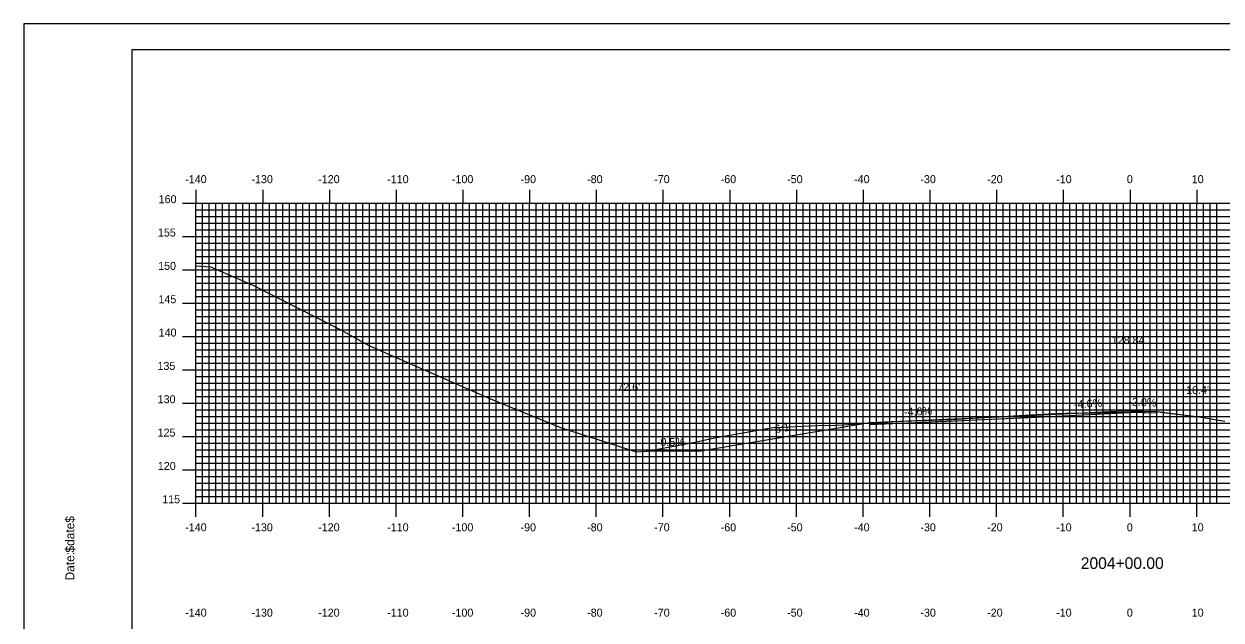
# Model space of a CAD drawing. Extents: x 851533 to 851876, y 366605 to 366825.
# Drawn here: x 851532.7 to 851712.1, y 366735.5 to 366824.9 of the extents above; entities that cross this region are included whole.
import ezdxf

# ---------------------------------------------------------------- set-up
doc = ezdxf.new("R2010")
doc.units = 0
for name, color, linetype in [('ANNOTATION', 7, 'Continuous'), ('BORDER', 7, 'Continuous'), ('D_Roadway_Centerline_Text', 7, 'Continuous'), ('D_Roadway_Edge_Shoulder', 7, 'Continuous'), ('D_Roadway_Edge_TW', 7, 'Continuous'), ('D_Roadway_SlopeLines', 7, 'Continuous'), ('D_Text_Standard', 7, 'Continuous'), ('H_V ANNOTATION', 7, 'Continuous'), ('M_Roadway_Centerline', 7, 'Continuous'), ('MAJOR', 7, 'Continuous'), ('MINOR', 7, 'Continuous'), ('PLOT BOUNDARY', 7, 'Continuous'), ('S_Roadway_Centerline', 7, 'Continuous')]:
    doc.layers.add(name, color=color, linetype=linetype)

msp = doc.modelspace()

# ---------------------------------------------------------------- linework, layer by layer
at = {"layer": 'BORDER'}
msp.add_lwpolyline([(851548.85, 366611.06), (851868.85, 366611.06), (851868.85, 366821.06), (851548.85, 366821.06)], close=True, dxfattribs=at)
at = {"layer": 'D_Roadway_Edge_Shoulder'}
for points in [[(851698.45, 366766.9), (851702.45, 366766.82), (851702.45, 366766.57), (851698.45, 366766.65)], [(851667.46, 366765.47), (851659.46, 366765.1), (851659.46, 366764.85), (851667.46, 366765.22)]]:
    msp.add_lwpolyline(points, close=True, dxfattribs=at)
at = {"layer": 'D_Roadway_Edge_TW'}
for points in [[(851698.45, 366766.9), (851686.45, 366766.34), (851686.45, 366766.09), (851698.45, 366766.65)], [(851674.45, 366765.79), (851667.46, 366765.47), (851667.46, 366765.22), (851674.45, 366765.54)], [(851686.45, 366766.34), (851674.45, 366765.79), (851674.45, 366765.54), (851686.45, 366766.09)]]:
    msp.add_lwpolyline(points, close=True, dxfattribs=at)
msp.add_lwpolyline([(851674.45, 366765.54), (851674.45, 366765.79)], dxfattribs=at)
at = {"layer": 'D_Roadway_SlopeLines'}
msp.add_line((851702.45, 366766.82), (851708.81, 366766), dxfattribs=at)
for points in [[(851659.46, 366765.1), (851633.83, 366760.83)], [(851633.83, 366760.83), (851625.88, 366760.87)]]:
    msp.add_lwpolyline(points, dxfattribs=at)
at = {"layer": 'MAJOR'}
for p, q in [((851558.45, 366800.06), (851558.45, 366798.06)), ((851568.45, 366800.06), (851568.45, 366798.06)), ((851578.45, 366800.06), (851578.45, 366798.06)), ((851588.45, 366800.06), (851588.45, 366798.06)), ((851598.45, 366800.06), (851598.45, 366798.06)), ((851608.45, 366800.06), (851608.45, 366798.06)), ((851618.45, 366800.06), (851618.45, 366798.06)), ((851628.45, 366800.06), (851628.45, 366798.06)), ((851638.45, 366800.06), (851638.45, 366798.06)), ((851648.45, 366800.06), (851648.45, 366798.06)), ((851658.45, 366800.06), (851658.45, 366798.06)), ((851668.45, 366800.06), (851668.45, 366798.06)), ((851678.45, 366800.06), (851678.45, 366798.06)), ((851688.45, 366800.06), (851688.45, 366798.06)), ((851698.45, 366800.06), (851698.45, 366798.06)), ((851708.45, 366800.06), (851708.45, 366798.06)), ((851556.45, 366798.06), (851558.45, 366798.06)), ((851558.45, 366798.06), (851838.45, 366798.06)), ((851558.45, 366753.06), (851558.45, 366798.06)), ((851558.45, 366753.06), (851558.45, 366798.06)), ((851558.45, 366798.06), (851838.45, 366798.06)), ((851568.45, 366753.06), (851568.45, 366798.06)), ((851578.45, 366753.06), (851578.45, 366798.06)), ((851588.45, 366753.06), (851588.45, 366798.06)), ((851598.45, 366753.06), (851598.45, 366798.06)), ((851608.45, 366753.06), (851608.45, 366798.06)), ((851618.45, 366753.06), (851618.45, 366798.06)), ((851628.45, 366753.06), (851628.45, 366798.06)), ((851638.45, 366753.06), (851638.45, 366798.06)), ((851648.45, 366753.06), (851648.45, 366798.06)), ((851658.45, 366753.06), (851658.45, 366798.06)), ((851668.45, 366753.06), (851668.45, 366798.06)), ((851678.45, 366753.06), (851678.45, 366798.06)), ((851688.45, 366753.06), (851688.45, 366798.06)), ((851698.45, 366753.06), (851698.45, 366798.06)), ((851708.45, 366753.06), (851708.45, 366798.06)), ((851556.45, 366793.06), (851558.45, 366793.06)), ((851558.45, 366793.06), (851838.45, 366793.06)), ((851556.45, 366788.06), (851558.45, 366788.06)), ((851558.45, 366788.06), (851838.45, 366788.06)), ((851556.45, 366783.06), (851558.45, 366783.06)), ((851558.45, 366783.06), (851838.45, 366783.06)), ((851556.45, 366778.06), (851558.45, 366778.06)), ((851558.45, 366778.06), (851838.45, 366778.06)), ((851556.45, 366773.06), (851558.45, 366773.06)), ((851558.45, 366773.06), (851838.45, 366773.06)), ((851556.45, 366768.06), (851558.45, 366768.06)), ((851558.45, 366768.06), (851838.45, 366768.06)), ((851556.45, 366763.06), (851558.45, 366763.06)), ((851558.45, 366763.06), (851838.45, 366763.06)), ((851556.45, 366758.06), (851558.45, 366758.06)), ((851558.45, 366758.06), (851838.45, 366758.06)), ((851556.45, 366753.06), (851558.45, 366753.06)), ((851558.45, 366753.06), (851838.45, 366753.06)), ((851558.45, 366753.06), (851838.45, 366753.06)), ((851558.45, 366751.05), (851558.45, 366753.06)), ((851568.45, 366751.05), (851568.45, 366753.06)), ((851578.45, 366751.05), (851578.45, 366753.06)), ((851588.45, 366751.05), (851588.45, 366753.06)), ((851598.45, 366751.05), (851598.45, 366753.06)), ((851608.45, 366751.05), (851608.45, 366753.06)), ((851618.45, 366751.05), (851618.45, 366753.06)), ((851628.45, 366751.05), (851628.45, 366753.06)), ((851638.45, 366751.05), (851638.45, 366753.06)), ((851648.45, 366751.05), (851648.45, 366753.06)), ((851658.45, 366751.05), (851658.45, 366753.06)), ((851668.45, 366751.05), (851668.45, 366753.06)), ((851678.45, 366751.05), (851678.45, 366753.06)), ((851688.45, 366751.05), (851688.45, 366753.06)), ((851698.45, 366751.05), (851698.45, 366753.06)), ((851708.45, 366751.05), (851708.45, 366753.06))]:
    msp.add_line(p, q, dxfattribs=at)
at = {"layer": 'MINOR'}
for p, q in [((851559.45, 366753.06), (851559.45, 366798.06)), ((851560.45, 366753.06), (851560.45, 366798.06)), ((851561.45, 366753.06), (851561.45, 366798.06)), ((851562.45, 366753.06), (851562.45, 366798.06)), ((851563.45, 366753.06), (851563.45, 366798.06)), ((851564.45, 366753.06), (851564.45, 366798.06)), ((851565.45, 366753.06), (851565.45, 366798.06)), ((851566.45, 366753.06), (851566.45, 366798.06)), ((851567.45, 366753.06), (851567.45, 366798.06)), ((851569.45, 366753.06), (851569.45, 366798.06)), ((851570.45, 366753.06), (851570.45, 366798.06)), ((851571.45, 366753.06), (851571.45, 366798.06)), ((851572.45, 366753.06), (851572.45, 366798.06)), ((851573.45, 366753.06), (851573.45, 366798.06)), ((851574.45, 366753.06), (851574.45, 366798.06)), ((851575.45, 366753.06), (851575.45, 366798.06)), ((851576.45, 366753.06), (851576.45, 366798.06)), ((851577.45, 366753.06), (851577.45, 366798.06)), ((851579.45, 366753.06), (851579.45, 366798.06)), ((851580.45, 366753.06), (851580.45, 366798.06)), ((851581.45, 366753.06), (851581.45, 366798.06)), ((851582.45, 366753.06), (851582.45, 366798.06)), ((851583.45, 366753.06), (851583.45, 366798.06)), ((851584.45, 366753.06), (851584.45, 366798.06)), ((851585.45, 366753.06), (851585.45, 366798.06)), ((851586.45, 366753.06), (851586.45, 366798.06)), ((851587.45, 366753.06), (851587.45, 366798.06)), ((851589.45, 366753.06), (851589.45, 366798.06)), ((851590.45, 366753.06), (851590.45, 366798.06)), ((851591.45, 366753.06), (851591.45, 366798.06)), ((851592.45, 366753.06), (851592.45, 366798.06)), ((851593.45, 366753.06), (851593.45, 366798.06)), ((851594.45, 366753.06), (851594.45, 366798.06)), ((851595.45, 366753.06), (851595.45, 366798.06)), ((851596.45, 366753.06), (851596.45, 366798.06)), ((851597.45, 366753.06), (851597.45, 366798.06)), ((851599.45, 366753.06), (851599.45, 366798.06)), ((851600.45, 366753.06), (851600.45, 366798.06)), ((851601.45, 366753.06), (851601.45, 366798.06)), ((851602.45, 366753.06), (851602.45, 366798.06)), ((851603.45, 366753.06), (851603.45, 366798.06)), ((851604.45, 366753.06), (851604.45, 366798.06)), ((851605.45, 366753.06), (851605.45, 366798.06)), ((851606.45, 366753.06), (851606.45, 366798.06)), ((851607.45, 366753.06), (851607.45, 366798.06)), ((851609.45, 366753.06), (851609.45, 366798.06)), ((851610.45, 366753.06), (851610.45, 366798.06)), ((851611.45, 366753.06), (851611.45, 366798.06)), ((851612.45, 366753.06), (851612.45, 366798.06)), ((851613.45, 366753.06), (851613.45, 366798.06)), ((851614.45, 366753.06), (851614.45, 366798.06)), ((851615.45, 366753.06), (851615.45, 366798.06)), ((851616.45, 366753.06), (851616.45, 366798.06)), ((851617.45, 366753.06), (851617.45, 366798.06)), ((851619.45, 366753.06), (851619.45, 366798.06)), ((851620.45, 366753.06), (851620.45, 366798.06)), ((851621.45, 366753.06), (851621.45, 366798.06)), ((851622.45, 366753.06), (851622.45, 366798.06)), ((851623.45, 366753.06), (851623.45, 366798.06)), ((851624.45, 366753.06), (851624.45, 366798.06)), ((851625.45, 366753.06), (851625.45, 366798.06)), ((851626.45, 366753.06), (851626.45, 366798.06)), ((851627.45, 366753.06), (851627.45, 366798.06)), ((851629.45, 366753.06), (851629.45, 366798.06)), ((851630.45, 366753.06), (851630.45, 366798.06)), ((851631.45, 366753.06), (851631.45, 366798.06)), ((851632.45, 366753.06), (851632.45, 366798.06)), ((851633.45, 366753.06), (851633.45, 366798.06)), ((851634.45, 366753.06), (851634.45, 366798.06)), ((851635.45, 366753.06), (851635.45, 366798.06)), ((851636.45, 366753.06), (851636.45, 366798.06)), ((851637.45, 366753.06), (851637.45, 366798.06)), ((851639.45, 366753.06), (851639.45, 366798.06)), ((851640.45, 366753.06), (851640.45, 366798.06)), ((851641.45, 366753.06), (851641.45, 366798.06)), ((851642.45, 366753.06), (851642.45, 366798.06)), ((851643.45, 366753.06), (851643.45, 366798.06)), ((851644.45, 366753.06), (851644.45, 366798.06)), ((851645.45, 366753.06), (851645.45, 366798.06)), ((851646.45, 366753.06), (851646.45, 366798.06)), ((851647.45, 366753.06), (851647.45, 366798.06)), ((851649.45, 366753.06), (851649.45, 366798.06)), ((851650.45, 366753.06), (851650.45, 366798.06)), ((851651.45, 366753.06), (851651.45, 366798.06)), ((851652.45, 366753.06), (851652.45, 366798.06)), ((851653.45, 366753.06), (851653.45, 366798.06)), ((851654.45, 366753.06), (851654.45, 366798.06)), ((851655.45, 366753.06), (851655.45, 366798.06)), ((851656.45, 366753.06), (851656.45, 366798.06)), ((851657.45, 366753.06), (851657.45, 366798.06)), ((851659.45, 366753.06), (851659.45, 366798.06)), ((851660.45, 366753.06), (851660.45, 366798.06)), ((851661.45, 366753.06), (851661.45, 366798.06)), ((851662.45, 366753.06), (851662.45, 366798.06)), ((851663.45, 366753.06), (851663.45, 366798.06)), ((851664.45, 366753.06), (851664.45, 366798.06)), ((851665.45, 366753.06), (851665.45, 366798.06)), ((851666.45, 366753.06), (851666.45, 366798.06)), ((851667.45, 366753.06), (851667.45, 366798.06)), ((851669.45, 366753.06), (851669.45, 366798.06)), ((851670.45, 366753.06), (851670.45, 366798.06)), ((851671.45, 366753.06), (851671.45, 366798.06)), ((851672.45, 366753.06), (851672.45, 366798.06)), ((851673.45, 366753.06), (851673.45, 366798.06)), ((851674.45, 366753.06), (851674.45, 366798.06)), ((851675.45, 366753.06), (851675.45, 366798.06)), ((851676.45, 366753.06), (851676.45, 366798.06)), ((851677.45, 366753.06), (851677.45, 366798.06)), ((851679.45, 366753.06), (851679.45, 366798.06)), ((851680.45, 366753.06), (851680.45, 366798.06)), ((851681.45, 366753.06), (851681.45, 366798.06)), ((851682.45, 366753.06), (851682.45, 366798.06)), ((851683.45, 366753.06), (851683.45, 366798.06)), ((851684.45, 366753.06), (851684.45, 366798.06)), ((851685.45, 366753.06), (851685.45, 366798.06)), ((851686.45, 366753.06), (851686.45, 366798.06)), ((851687.45, 366753.06), (851687.45, 366798.06)), ((851689.45, 366753.06), (851689.45, 366798.06)), ((851690.45, 366753.06), (851690.45, 366798.06)), ((851691.45, 366753.06), (851691.45, 366798.06)), ((851692.45, 366753.06), (851692.45, 366798.06)), ((851693.45, 366753.06), (851693.45, 366798.06)), ((851694.45, 366753.06), (851694.45, 366798.06)), ((851695.45, 366753.06), (851695.45, 366798.06)), ((851696.45, 366753.06), (851696.45, 366798.06)), ((851697.45, 366753.06), (851697.45, 366798.06)), ((851699.45, 366753.06), (851699.45, 366798.06)), ((851700.45, 366753.06), (851700.45, 366798.06)), ((851701.45, 366753.06), (851701.45, 366798.06)), ((851702.45, 366753.06), (851702.45, 366798.06)), ((851703.45, 366753.06), (851703.45, 366798.06)), ((851704.45, 366753.06), (851704.45, 366798.06)), ((851705.45, 366753.06), (851705.45, 366798.06)), ((851706.45, 366753.06), (851706.45, 366798.06)), ((851707.45, 366753.06), (851707.45, 366798.06)), ((851709.45, 366753.06), (851709.45, 366798.06)), ((851710.45, 366753.06), (851710.45, 366798.06)), ((851711.45, 366753.06), (851711.45, 366798.06)), ((851558.45, 366797.06), (851838.45, 366797.06)), ((851558.45, 366797.06), (851560.46, 366797.06)), ((851558.45, 366796.06), (851838.45, 366796.06)), ((851558.45, 366796.06), (851560.46, 366796.06)), ((851558.45, 366795.06), (851838.45, 366795.06)), ((851558.45, 366795.06), (851560.46, 366795.06)), ((851558.45, 366794.06), (851838.45, 366794.06)), ((851558.45, 366794.06), (851560.46, 366794.06)), ((851558.45, 366792.06), (851838.45, 366792.06)), ((851558.45, 366792.06), (851560.46, 366792.06)), ((851558.45, 366791.06), (851838.45, 366791.06)), ((851558.45, 366791.06), (851560.46, 366791.06)), ((851558.45, 366790.06), (851838.45, 366790.06)), ((851558.45, 366790.06), (851560.46, 366790.06)), ((851558.45, 366789.06), (851838.45, 366789.06)), ((851558.45, 366789.06), (851560.46, 366789.06)), ((851558.45, 366787.06), (851838.45, 366787.06)), ((851558.45, 366787.06), (851560.46, 366787.06)), ((851558.45, 366786.06), (851838.45, 366786.06)), ((851558.45, 366786.06), (851560.46, 366786.06)), ((851558.45, 366785.06), (851838.45, 366785.06)), ((851558.45, 366785.06), (851560.46, 366785.06)), ((851558.45, 366784.06), (851838.45, 366784.06)), ((851558.45, 366784.06), (851560.46, 366784.06)), ((851558.45, 366782.06), (851838.45, 366782.06)), ((851558.45, 366782.06), (851560.46, 366782.06)), ((851558.45, 366781.06), (851838.45, 366781.06)), ((851558.45, 366781.06), (851560.46, 366781.06)), ((851558.45, 366780.06), (851838.45, 366780.06)), ((851558.45, 366780.06), (851560.46, 366780.06)), ((851558.45, 366779.06), (851838.45, 366779.06)), ((851558.45, 366779.06), (851560.46, 366779.06)), ((851558.45, 366777.06), (851838.45, 366777.06)), ((851558.45, 366777.06), (851560.46, 366777.06)), ((851558.45, 366776.06), (851838.45, 366776.06)), ((851558.45, 366776.06), (851560.46, 366776.06)), ((851558.45, 366775.06), (851838.45, 366775.06)), ((851558.45, 366775.06), (851560.46, 366775.06)), ((851558.45, 366774.06), (851838.45, 366774.06)), ((851558.45, 366774.06), (851560.46, 366774.06)), ((851558.45, 366772.06), (851838.45, 366772.06)), ((851558.45, 366772.06), (851560.46, 366772.06)), ((851558.45, 366771.06), (851838.45, 366771.06)), ((851558.45, 366771.06), (851560.46, 366771.06)), ((851558.45, 366770.06), (851838.45, 366770.06)), ((851558.45, 366770.06), (851560.46, 366770.06)), ((851558.45, 366769.06), (851838.45, 366769.06)), ((851558.45, 366769.06), (851560.46, 366769.06)), ((851558.45, 366767.06), (851838.45, 366767.06)), ((851558.45, 366767.06), (851560.46, 366767.06)), ((851558.45, 366766.06), (851838.45, 366766.06)), ((851558.45, 366766.06), (851560.46, 366766.06)), ((851558.45, 366765.06), (851838.45, 366765.06)), ((851558.45, 366765.06), (851560.46, 366765.06)), ((851558.45, 366764.06), (851838.45, 366764.06)), ((851558.45, 366764.06), (851560.46, 366764.06)), ((851558.45, 366762.06), (851838.45, 366762.06)), ((851558.45, 366762.06), (851560.46, 366762.06)), ((851558.45, 366761.06), (851838.45, 366761.06)), ((851558.45, 366761.06), (851560.46, 366761.06)), ((851558.45, 366760.06), (851838.45, 366760.06)), ((851558.45, 366760.06), (851560.46, 366760.06)), ((851558.45, 366759.06), (851838.45, 366759.06)), ((851558.45, 366759.06), (851560.46, 366759.06)), ((851558.45, 366757.06), (851838.45, 366757.06)), ((851558.45, 366757.06), (851560.46, 366757.06)), ((851558.45, 366756.06), (851838.45, 366756.06)), ((851558.45, 366756.06), (851560.46, 366756.06)), ((851558.45, 366755.06), (851838.45, 366755.06)), ((851558.45, 366755.06), (851560.46, 366755.06)), ((851558.45, 366754.06), (851838.45, 366754.06)), ((851558.45, 366754.06), (851560.46, 366754.06))]:
    msp.add_line(p, q, dxfattribs=at)
at = {"layer": 'PLOT BOUNDARY'}
msp.add_lwpolyline([(851532.66, 366604.94), (851872.66, 366604.94), (851872.66, 366824.94), (851532.66, 366824.94)], close=True, dxfattribs=at)
at = {"layer": 'S_Roadway_Centerline'}
msp.add_lwpolyline([(851558.45, 366788.68), (851560.64, 366788.51), (851566.86, 366785.81), (851580.18, 366779.05), (851584.36, 366776.7), (851589.27, 366774.56), (851602.6, 366768.71), (851613.08, 366764.42), (851624.42, 366760.76), (851625.88, 366760.87), (851626.09, 366760.85), (851633.48, 366762.29), (851636.18, 366762.88), (851644.96, 366764.4), (851646.3, 366764.48), (851651.66, 366764.71), (851654.54, 366764.78), (851660.91, 366765.18), (851662.76, 366765.32), (851671.75, 366765.64), (851672.5, 366765.67), (851673.21, 366765.71), (851686.18, 366766.47), (851688.82, 366766.57), (851690.57, 366766.58), (851693.96, 366766.6), (851702.38, 366766.86), (851703.03, 366766.72), (851708.81, 366766), (851712.64, 366765.37)], dxfattribs=at)

# ---------------------------------------------------------------- texts
at = {"layer": 'ANNOTATION'}
for s, rotation, p in [('-4.6%', 2.6337, (851690.09, 366767.31)), ('-2.0%', 357.7098, (851698.19, 366767.71)), ('-4.6%', 2.6358, (851664.6, 366766.14)), ('6:1', 9.4613, (851645.32, 366763.57)), ('-0.5%', 359.7408, (851627.53, 366761.66))]:
    msp.add_text(s, height=1.2, rotation=rotation, dxfattribs=at).set_placement(p)
at = {"layer": 'BORDER'}
for s, p in [('$date$', (851540.22, 366745.67)), ('Date:', (851540.22, 366741.49))]:
    msp.add_text(s, height=1.339, rotation=90, dxfattribs=at).set_placement(p)
at = {"layer": 'D_Roadway_Centerline_Text'}
msp.add_text('128.84', height=1.2, dxfattribs=at).set_placement((851695.71, 366776.93))
at = {"layer": 'D_Text_Standard'}
for s, p in [("72.6'", (851621.6, 366769.9)), ("10.4'", (851706.86, 366769.45))]:
    msp.add_text(s, height=1.2, dxfattribs=at).set_placement(p)
at = {"layer": 'H_V ANNOTATION'}
for s, height, p in [('-140', 1.2, (851556.84, 366801.06)), ('-130', 1.2, (851566.76, 366801.06)), ('-120', 1.2, (851576.77, 366801.06)), ('-110', 1.2, (851587.11, 366801.06)), ('-100', 1.2, (851596.81, 366801.06)), ('-90', 1.2, (851607.1, 366801.06)), ('-80', 1.2, (851617.08, 366801.06)), ('-70', 1.2, (851627.13, 366801.06)), ('-60', 1.2, (851637.1, 366801.06)), ('-50', 1.2, (851647.06, 366801.06)), ('-40', 1.2, (851657.1, 366801.06)), ('-30', 1.2, (851667.03, 366801.06)), ('-20', 1.2, (851677.04, 366801.06)), ('-10', 1.2, (851687.38, 366801.06)), ('0', 1.2, (851697.97, 366801.06)), ('10', 1.2, (851707.7, 366801.06)), ('160', 1.2, (851552.86, 366798.06)), ('155', 1.2, (851552.74, 366793.06)), ('150', 1.2, (851552.78, 366788.06)), ('145', 1.2, (851552.83, 366783.06)), ('140', 1.2, (851552.86, 366778.06)), ('135', 1.2, (851552.68, 366773.06)), ('130', 1.2, (851552.71, 366768.06)), ('125', 1.2, (851552.7, 366763.06)), ('120', 1.2, (851552.73, 366758.06)), ('115', 1.2, (851553.39, 366753.06)), ('-140', 1.2, (851556.84, 366748.86)), ('-130', 1.2, (851566.76, 366748.86)), ('-120', 1.2, (851576.77, 366748.86)), ('-110', 1.2, (851587.11, 366748.86)), ('-100', 1.2, (851596.81, 366748.86)), ('-90', 1.2, (851607.1, 366748.86)), ('-80', 1.2, (851617.08, 366748.86)), ('-70', 1.2, (851627.13, 366748.86)), ('-60', 1.2, (851637.1, 366748.86)), ('-50', 1.2, (851647.06, 366748.86)), ('-40', 1.2, (851657.1, 366748.86)), ('-30', 1.2, (851667.03, 366748.86)), ('-20', 1.2, (851677.04, 366748.86)), ('-10', 1.2, (851687.38, 366748.86)), ('0', 1.2, (851697.97, 366748.86)), ('10', 1.2, (851707.7, 366748.86)), ('2004+00.00', 1.75, (851691.07, 366743.21)), ('-140', 1.2, (851556.84, 366736.06)), ('-130', 1.2, (851566.76, 366736.06)), ('-120', 1.2, (851576.77, 366736.06)), ('-110', 1.2, (851587.11, 366736.06)), ('-100', 1.2, (851596.81, 366736.06)), ('-90', 1.2, (851607.1, 366736.06)), ('-80', 1.2, (851617.08, 366736.06)), ('-70', 1.2, (851627.13, 366736.06)), ('-60', 1.2, (851637.1, 366736.06)), ('-50', 1.2, (851647.06, 366736.06)), ('-40', 1.2, (851657.1, 366736.06)), ('-30', 1.2, (851667.03, 366736.06)), ('-20', 1.2, (851677.04, 366736.06)), ('-10', 1.2, (851687.38, 366736.06)), ('0', 1.2, (851697.97, 366736.06)), ('10', 1.2, (851707.7, 366736.06))]:
    msp.add_text(s, height=height, dxfattribs=at).set_placement(p)
at = {"layer": 'M_Roadway_Centerline'}
for s, p in [('C', (851662.75, 366765.32)), ('L', (851662.76, 366765.31)), ('C', (851686.17, 366766.47)), ('L', (851686.18, 366766.46))]:
    msp.add_text(s, height=0.0146, dxfattribs=at).set_placement(p)
at = {"layer": 'MAJOR'}
msp.add_text('-', height=0.012, dxfattribs=at).set_placement((851558.44, 366753.06))

doc.saveas('drawing.dxf')
